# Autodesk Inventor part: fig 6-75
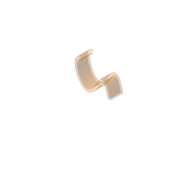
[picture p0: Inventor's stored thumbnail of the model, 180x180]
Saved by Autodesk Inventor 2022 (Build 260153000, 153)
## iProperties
Part Number: fig 6-75
Document SubType Name: Modeling
Created: 2002-12
Designer: deepak
Density: 1 g/cm^3
Material: Generic
Appearance: Default
Control State: 0
Master: False
Checked Out: False
Shininess: 64.0
Length Units: 11269
Angle Units: 11279
Time Units: 11290
Mass Units: 11283
Length Display Precision: 3
Angle Display Precision: 2
Compacted: True
Density: 0.0
Volumn: 0.0
Area: 0.0
PropertySet Name: Model Information
Author: deepak
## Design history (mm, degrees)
sketch "Sketch1"
  geometry: 5 further points
  constraints: 5 other
extrude_surface "ExtrusionSrf1" sketch "Sketch1" dims "d0" = 20, "d1" = 0
feature "OffsetSrf2" dims "d8" = 4, "d9" = 4
body "Solid1"
body "Srf1"
body "Srf2"
